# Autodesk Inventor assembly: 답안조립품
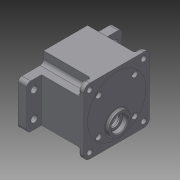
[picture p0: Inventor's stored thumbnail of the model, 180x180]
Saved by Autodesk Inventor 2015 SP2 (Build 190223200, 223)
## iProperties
Created: 2015-06
Part Number: 답안조립품
Document SubType Name: Assembly
Designer: AMC
Author: AMC
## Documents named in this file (8)
- C:\Users\AMC\Desktop\450620V1014\답안조립품.iam
- C:\Users\AMC\Desktop\450620V1014\본체.ipt
- C:\Users\AMC\Desktop\450620V1014\오일실 17x32x8.ipt
- C:\Users\AMC\Desktop\450620V1014\베어링 6003.ipt
- 베어링 6003.ipt
- C:\Users\AMC\Desktop\450620V1014\베어링 608.ipt
- 베어링 608.ipt
- C:\Users\AMC\Desktop\450620V1014\커버.ipt
